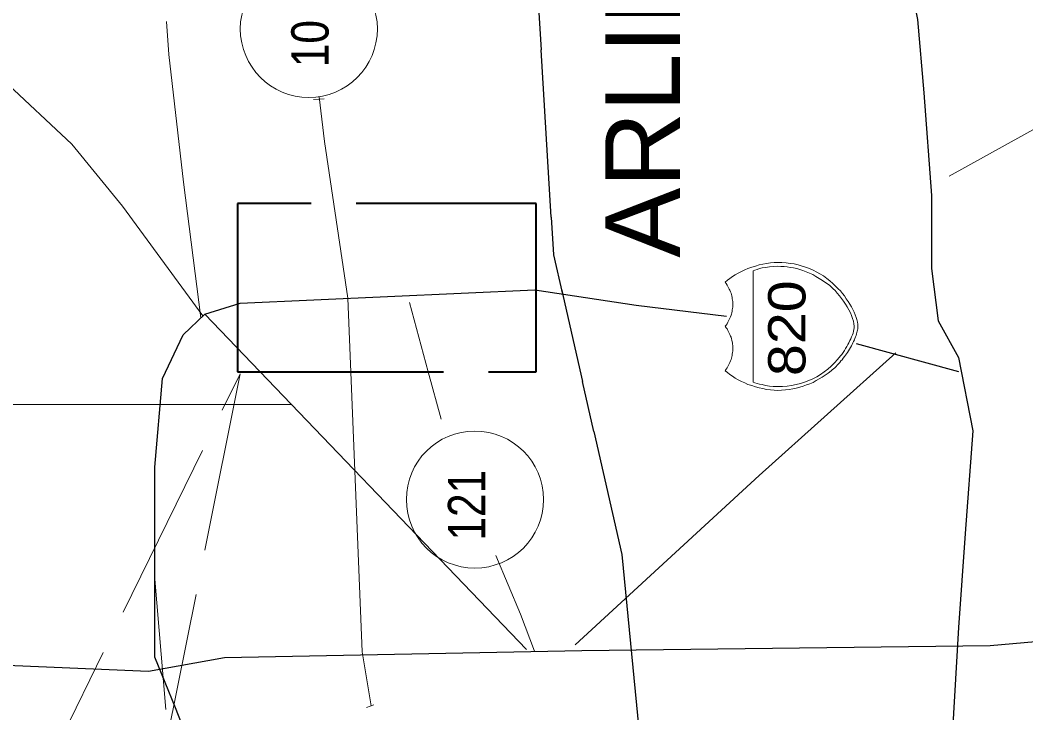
# Model space of a CAD drawing. Extents: x 2363323 to 2367082, y 6956018 to 6980837.
# Drawn here: x 2365927 to 2366064.3, y 6980582.6 to 6980677.3 of the extents above; entities that cross this region are included whole.
import ezdxf

# ---------------------------------------------------------------- set-up
doc = ezdxf.new("R2010")
doc.units = 0
doc.header["$LTSCALE"] = 4.1
doc.linetypes.add('LONG_DASHED', pattern=[7.5, 6, -1.5])
doc.layers.add('62', color=7, linetype='Continuous', lineweight=13)
doc.layers.add('63', color=7, linetype='Continuous', lineweight=13)

msp = doc.modelspace()

# ---------------------------------------------------------------- linework, layer by layer
at = {"layer": '62'}
for p, q in [((2365947.29, 6980672.631), (2365946.952, 6980677.108)), ((2365934.012, 6980660.367), (2365924.697, 6980669.121)), ((2365968.552, 6980660.704), (2365967.789, 6980666.826)), ((2365967.022, 6980666.444), (2365968.484, 6980666.534)), ((2365982.712, 6980629.248), (2365980.144, 6980638.72)), ((2365952.196, 6980637.146), (2365996.139, 6980591.308)), ((2365984.463, 6980622.789), (2365982.712, 6980629.248)), ((2365964.032, 6980624.792), (2365920.176, 6980624.792)), ((2365995.308, 6980596.125), (2365991.957, 6980604.156)), ((2365946.84, 6980583.093), (2365945.334, 6980601.436)), ((2365995.308, 6980596.125), (2365997.22, 6980591.061)), ((2365974.27, 6980583.364), (2365975.283, 6980583.724))]:
    msp.add_line(p, q, dxfattribs=at)
at = {"layer": '62', "lineweight": 25}
for p, q in [((2365999.516, 6980650.396), (2365998.12, 6980673.24)), ((2365957.033, 6980638.607), (2365997.267, 6980640.453)), ((2366000.89, 6980640.543), (2366003.771, 6980627.919)), ((2365952.196, 6980637.146), (2365957.032, 6980638.608)), ((2366041.17, 6980633.096), (2366055.164, 6980629.294)), ((2366005.324, 6980621.103), (2366003.771, 6980627.919))]:
    msp.add_line(p, q, dxfattribs=at)
for points in [[(2365988.154, 6980835.546), (2365989.437, 6980822.404), (2365992.248, 6980802.402), (2365995.06, 6980778.345), (2365996.118, 6980752.4), (2365996.118, 6980723.35), (2365996.997, 6980691.422), (2365998.12, 6980673.24)], [(2366048.01, 6980685.208), (2366049.539, 6980677.378), (2366050.418, 6980667.388), (2366051.476, 6980653.346), (2366051.474, 6980643.356), (2366052.352, 6980636.2), (2366055.164, 6980631.206), (2366057.122, 6980621.192), (2366056.064, 6980607.15), (2366055.164, 6980594.301), (2366054.309, 6980580.237), (2366057.123, 6980558.096), (2366054.309, 6980537.146), (2366050.416, 6980520.246), (2366044.949, 6980510.235), (2366031.738, 6980507.152), (2366018.51, 6980507.151), (2366011.984, 6980505.261), (2366002.646, 6980510.235)], [(2365999.516, 6980650.396), (2365999.808, 6980645.246), (2366001.047, 6980639.868)], [(2365997.267, 6980640.453), (2366011.106, 6980638.338), (2366023.46, 6980636.853)], [(2365973.55, 6980527.155), (2365967.024, 6980537.146), (2365962.275, 6980551.21), (2365957.528, 6980561.2), (2365952.939, 6980571.213), (2365948.169, 6980583.344), (2365945.355, 6980590.252), (2365945.356, 6980600.244), (2365945.356, 6980616.195), (2365946.412, 6980628.348), (2365949.226, 6980634.288), (2365952.196, 6980637.146)], [(2366005.324, 6980621.103), (2366009.171, 6980604.292), (2366011.985, 6980575.242), (2366017.632, 6980553.099), (2366018.038, 6980546.259)], [(2365954.874, 6980590.182), (2366003.705, 6980591.15), (2366059.484, 6980591.828), (2366130.702, 6980598.128), (2366162.138, 6980614.575)], [(2365899.359, 6980590.251), (2365944.478, 6980588.34), (2365954.874, 6980590.182)]]:
    msp.add_lwpolyline(points, dxfattribs=at)
at = {"layer": '62'}
for points in [[(2366168.8, 6980776.882), (2366165.783, 6980768.805), (2366163.94, 6980759.174), (2366160.383, 6980741.87), (2366154.128, 6980731.611), (2366149.72, 6980724.7), (2366143.802, 6980715.788), (2366134.416, 6980706.992), (2366124.222, 6980700.849), (2366112.792, 6980694.908), (2366099.244, 6980686.448), (2366090.672, 6980679.021), (2366082.168, 6980673.328), (2366071.481, 6980667.05), (2366066.596, 6980663.068), (2366053.86, 6980656.002)], [(2365951.632, 6980636.606), (2365949.27, 6980655.168), (2365947.29, 6980672.631)], [(2365934.012, 6980660.367), (2365940.946, 6980651.904), (2365951.902, 6980636.876)], [(2365968.552, 6980660.704), (2365971.728, 6980639.328), (2365973.664, 6980590.971), (2365974.902, 6980583.59)], [(2366023.728, 6980636.2), (2366023.818, 6980636.403), (2366023.91, 6980636.584), (2366023.976, 6980636.763), (2366024.066, 6980636.966), (2366024.111, 6980637.146), (2366024.18, 6980637.326), (2366024.224, 6980637.53), (2366024.246, 6980637.708), (2366024.291, 6980637.91), (2366024.336, 6980638.089), (2366024.336, 6980638.293), (2366024.336, 6980638.496), (2366024.336, 6980638.653), (2366024.336, 6980638.856), (2366024.291, 6980639.058), (2366024.246, 6980639.238), (2366024.225, 6980639.42), (2366024.178, 6980639.62), (2366024.111, 6980639.802), (2366024.066, 6980639.98), (2366023.976, 6980640.184), (2366023.908, 6980640.386), (2366023.818, 6980640.543), (2366023.728, 6980640.746), (2366023.616, 6980640.926), (2366023.524, 6980641.106), (2366023.392, 6980641.306), (2366023.256, 6980641.51), (2366023.571, 6980641.76), (2366023.888, 6980642.006), (2366024.27, 6980642.276), (2366024.651, 6980642.5), (2366025.058, 6980642.726), (2366025.484, 6980642.973), (2366025.935, 6980643.176), (2366026.384, 6980643.356), (2366026.9, 6980643.536), (2366027.396, 6980643.693), (2366027.892, 6980643.85), (2366028.408, 6980643.963), (2366028.926, 6980644.054), (2366029.445, 6980644.12), (2366029.94, 6980644.166), (2366030.48, 6980644.19), (2366031.018, 6980644.166), (2366031.605, 6980644.12), (2366032.168, 6980644.053), (2366032.684, 6980643.987), (2366033.225, 6980643.873), (2366033.764, 6980643.694), (2366034.258, 6980643.537), (2366034.778, 6980643.356), (2366035.271, 6980643.153), (2366035.769, 6980642.884), (2366036.218, 6980642.636), (2366036.693, 6980642.343), (2366037.142, 6980642.006), (2366037.57, 6980641.69), (2366037.996, 6980641.308), (2366038.403, 6980640.927), (2366038.694, 6980640.61), (2366039.01, 6980640.296), (2366039.302, 6980639.958), (2366039.572, 6980639.62), (2366039.82, 6980639.236), (2366040.066, 6980638.856), (2366040.292, 6980638.496), (2366040.516, 6980638.113), (2366040.696, 6980637.776), (2366040.876, 6980637.416), (2366041.034, 6980637.033), (2366041.169, 6980636.674), (2366041.235, 6980636.38), (2366041.328, 6980636.043), (2366041.372, 6980635.752), (2366041.394, 6980635.48)], [(2366041.394, 6980635.48), (2366041.372, 6980635.302), (2366041.372, 6980635.143), (2366041.349, 6980634.94), (2366041.306, 6980634.783), (2366041.259, 6980634.603), (2366041.216, 6980634.423), (2366041.146, 6980634.222), (2366041.079, 6980634.016), (2366040.99, 6980633.817), (2366040.922, 6980633.613), (2366040.809, 6980633.388), (2366040.72, 6980633.21), (2366040.629, 6980632.983), (2366040.518, 6980632.78), (2366040.382, 6980632.556), (2366040.269, 6980632.354), (2366040.134, 6980632.128), (2366039.999, 6980631.903), (2366039.843, 6980631.702), (2366039.706, 6980631.52), (2366039.572, 6980631.318), (2366039.392, 6980631.093), (2366039.234, 6980630.89), (2366039.076, 6980630.733), (2366038.919, 6980630.508), (2366038.762, 6980630.35), (2366038.582, 6980630.148), (2366038.426, 6980629.99), (2366038.244, 6980629.81), (2366038.088, 6980629.653), (2366037.906, 6980629.518), (2366037.726, 6980629.36), (2366037.346, 6980629.066), (2366036.939, 6980628.774), (2366036.532, 6980628.526), (2366036.128, 6980628.302), (2366035.702, 6980628.054), (2366035.272, 6980627.806), (2366034.844, 6980627.626), (2366034.372, 6980627.448), (2366033.944, 6980627.268), (2366033.448, 6980627.133), (2366032.976, 6980627.019), (2366032.504, 6980626.908), (2366032.008, 6980626.816), (2366031.515, 6980626.772), (2366030.974, 6980626.728), (2366030.478, 6980626.704), (2366029.94, 6980626.726), (2366029.444, 6980626.772), (2366028.928, 6980626.84), (2366028.408, 6980626.952), (2366027.892, 6980627.043), (2366027.398, 6980627.2), (2366026.902, 6980627.356), (2366026.384, 6980627.516), (2366025.935, 6980627.718), (2366025.484, 6980627.919), (2366025.058, 6980628.142), (2366024.651, 6980628.392), (2366024.268, 6980628.639), (2366023.886, 6980628.864), (2366023.572, 6980629.136), (2366023.256, 6980629.384), (2366023.391, 6980629.586), (2366023.526, 6980629.788), (2366023.618, 6980629.968), (2366023.727, 6980630.148), (2366023.818, 6980630.35), (2366023.908, 6980630.53), (2366023.976, 6980630.733), (2366024.066, 6980630.936), (2366024.111, 6980631.093), (2366024.178, 6980631.296), (2366024.224, 6980631.476), (2366024.246, 6980631.676), (2366024.291, 6980631.88), (2366024.338, 6980632.06), (2366024.336, 6980632.24), (2366024.338, 6980632.443), (2366024.336, 6980632.623), (2366024.336, 6980632.826), (2366024.291, 6980633.007), (2366024.248, 6980633.208), (2366024.224, 6980633.366), (2366024.18, 6980633.568), (2366024.112, 6980633.77), (2366024.066, 6980633.973), (2366023.976, 6980634.13), (2366023.907, 6980634.333), (2366023.818, 6980634.536), (2366023.728, 6980634.716), (2366023.618, 6980634.897), (2366023.526, 6980635.098), (2366023.392, 6980635.257), (2366023.256, 6980635.48), (2366023.391, 6980635.638), (2366023.526, 6980635.818), (2366023.616, 6980636.02), (2366023.728, 6980636.2)], [(2366046.592, 6980631.836), (2366027.891, 6980615.072), (2366002.758, 6980591.916)]]:
    msp.add_lwpolyline(points, dxfattribs=at)
at = {"layer": '62', "linetype": 'LONG_DASHED', "lineweight": 40}
msp.add_lwpolyline([(2365960.182, 6980629.248), (2365997.468, 6980629.248), (2365997.47, 6980652.267), (2365956.652, 6980652.267), (2365956.65, 6980629.248)], close=True, dxfattribs=at)
at = {"layer": '62'}
msp.add_lwpolyline([(2366027.104, 6980643.063), (2366027.105, 6980627.829), (2366027.328, 6980627.76), (2366027.621, 6980627.648), (2366027.936, 6980627.56), (2366028.342, 6980627.492), (2366028.791, 6980627.379), (2366029.31, 6980627.266), (2366029.848, 6980627.244), (2366030.478, 6980627.222), (2366031.088, 6980627.244), (2366031.738, 6980627.265), (2366032.346, 6980627.38), (2366032.954, 6980627.492), (2366033.561, 6980627.649), (2366034.102, 6980627.829), (2366034.708, 6980628.054), (2366035.248, 6980628.303), (2366035.769, 6980628.573), (2366036.286, 6980628.886), (2366036.806, 6980629.227), (2366037.299, 6980629.587), (2366037.749, 6980630.014), (2366038.198, 6980630.463), (2366038.604, 6980630.934), (2366039.01, 6980631.43), (2366039.212, 6980631.632), (2366039.369, 6980631.903), (2366039.572, 6980632.173), (2366039.729, 6980632.443), (2366039.888, 6980632.69), (2366040.044, 6980632.96), (2366040.179, 6980633.23), (2366040.314, 6980633.523), (2366040.426, 6980633.772), (2366040.539, 6980634.018), (2366040.653, 6980634.288), (2366040.742, 6980634.536), (2366040.81, 6980634.784), (2366040.854, 6980635.008), (2366040.876, 6980635.254), (2366040.899, 6980635.482), (2366040.856, 6980635.796), (2366040.809, 6980636.178), (2366040.674, 6980636.516), (2366040.539, 6980636.943), (2366040.383, 6980637.303), (2366040.158, 6980637.708), (2366039.932, 6980638.113), (2366039.706, 6980638.496), (2366039.438, 6980638.924), (2366039.144, 6980639.283), (2366038.874, 6980639.643), (2366038.583, 6980640.003), (2366038.313, 6980640.34), (2366038.043, 6980640.61), (2366037.749, 6980640.88), (2366037.503, 6980641.083), (2366037.029, 6980641.42), (2366036.578, 6980641.736), (2366036.128, 6980642.006), (2366035.656, 6980642.276), (2366035.226, 6980642.524), (2366034.776, 6980642.726), (2366034.348, 6980642.928), (2366033.898, 6980643.086), (2366033.448, 6980643.243), (2366033.044, 6980643.356), (2366032.595, 6980643.468), (2366032.168, 6980643.513), (2366031.738, 6980643.58), (2366031.312, 6980643.626), (2366030.885, 6980643.648), (2366030.48, 6980643.67), (2366029.848, 6980643.648), (2366029.308, 6980643.603), (2366028.791, 6980643.513), (2366028.341, 6980643.468), (2366027.936, 6980643.357), (2366027.622, 6980643.243), (2366027.33, 6980643.154)], close=True, dxfattribs=at)
at = {"layer": '62', "linetype": 'LONG_DASHED'}
for points in [[(2365927.487, 6980568.808), (2365957.01, 6980628.978), (2365944.929, 6980568.537)], [(2365927.487, 6980568.808), (2365957.01, 6980628.978), (2365944.929, 6980568.537), (2365927.487, 6980568.808)]]:
    msp.add_lwpolyline(points, close=True, dxfattribs=at)
at = {"layer": '62'}
for centre in [(2365966.397, 6980676.102), (2365989.079, 6980611.787)]:
    msp.add_circle(centre, 9.364, dxfattribs=at)
at = {"layer": '63'}
for p, q in [((2365947.29, 6980672.631), (2365946.952, 6980677.108)), ((2365934.012, 6980660.367), (2365924.697, 6980669.121)), ((2365968.552, 6980660.704), (2365967.789, 6980666.826)), ((2365967.022, 6980666.444), (2365968.484, 6980666.534)), ((2365982.712, 6980629.248), (2365980.144, 6980638.72)), ((2365952.196, 6980637.146), (2365996.139, 6980591.308)), ((2365984.463, 6980622.789), (2365982.712, 6980629.248)), ((2365964.032, 6980624.792), (2365920.176, 6980624.792)), ((2365995.308, 6980596.125), (2365991.957, 6980604.156)), ((2365946.84, 6980583.093), (2365945.334, 6980601.436)), ((2365995.308, 6980596.125), (2365997.22, 6980591.061)), ((2365974.27, 6980583.364), (2365975.283, 6980583.724))]:
    msp.add_line(p, q, dxfattribs=at)
at = {"layer": '63', "lineweight": 25}
for p, q in [((2365999.516, 6980650.396), (2365998.12, 6980673.24)), ((2365957.033, 6980638.607), (2365997.267, 6980640.453)), ((2366000.89, 6980640.543), (2366003.771, 6980627.919)), ((2365952.196, 6980637.146), (2365957.032, 6980638.608)), ((2366041.17, 6980633.096), (2366055.164, 6980629.294)), ((2366005.324, 6980621.103), (2366003.771, 6980627.919))]:
    msp.add_line(p, q, dxfattribs=at)
for points in [[(2365988.154, 6980835.546), (2365989.437, 6980822.404), (2365992.248, 6980802.402), (2365995.06, 6980778.345), (2365996.118, 6980752.4), (2365996.118, 6980723.35), (2365996.997, 6980691.422), (2365998.12, 6980673.24)], [(2366048.01, 6980685.208), (2366049.539, 6980677.378), (2366050.418, 6980667.388), (2366051.476, 6980653.346), (2366051.474, 6980643.356), (2366052.352, 6980636.2), (2366055.164, 6980631.206), (2366057.122, 6980621.192), (2366056.064, 6980607.15), (2366055.164, 6980594.301), (2366054.309, 6980580.237), (2366057.123, 6980558.096), (2366054.309, 6980537.146), (2366050.416, 6980520.246), (2366044.949, 6980510.235), (2366031.738, 6980507.152), (2366018.51, 6980507.151), (2366011.984, 6980505.261), (2366002.646, 6980510.235)], [(2365999.516, 6980650.396), (2365999.808, 6980645.246), (2366001.047, 6980639.868)], [(2365997.267, 6980640.453), (2366011.106, 6980638.338), (2366023.46, 6980636.853)], [(2365973.55, 6980527.155), (2365967.024, 6980537.146), (2365962.275, 6980551.21), (2365957.528, 6980561.2), (2365952.939, 6980571.213), (2365948.169, 6980583.344), (2365945.355, 6980590.252), (2365945.356, 6980600.244), (2365945.356, 6980616.195), (2365946.412, 6980628.348), (2365949.226, 6980634.288), (2365952.196, 6980637.146)], [(2366005.324, 6980621.103), (2366009.171, 6980604.292), (2366011.985, 6980575.242), (2366017.632, 6980553.099), (2366018.038, 6980546.259)], [(2365954.874, 6980590.182), (2366003.705, 6980591.15), (2366059.484, 6980591.828), (2366130.702, 6980598.128), (2366162.138, 6980614.575)], [(2365899.359, 6980590.251), (2365944.478, 6980588.34), (2365954.874, 6980590.182)]]:
    msp.add_lwpolyline(points, dxfattribs=at)
at = {"layer": '63'}
for points in [[(2366168.8, 6980776.882), (2366165.783, 6980768.805), (2366163.94, 6980759.174), (2366160.383, 6980741.87), (2366154.128, 6980731.611), (2366149.72, 6980724.7), (2366143.802, 6980715.788), (2366134.416, 6980706.992), (2366124.222, 6980700.849), (2366112.792, 6980694.908), (2366099.244, 6980686.448), (2366090.672, 6980679.021), (2366082.168, 6980673.328), (2366071.481, 6980667.05), (2366066.596, 6980663.068), (2366053.86, 6980656.002)], [(2365951.632, 6980636.606), (2365949.27, 6980655.168), (2365947.29, 6980672.631)], [(2365934.012, 6980660.367), (2365940.946, 6980651.904), (2365951.902, 6980636.876)], [(2365968.552, 6980660.704), (2365971.728, 6980639.328), (2365973.664, 6980590.971), (2365974.902, 6980583.59)], [(2366023.728, 6980636.2), (2366023.818, 6980636.403), (2366023.91, 6980636.584), (2366023.976, 6980636.763), (2366024.066, 6980636.966), (2366024.111, 6980637.146), (2366024.18, 6980637.326), (2366024.224, 6980637.53), (2366024.246, 6980637.708), (2366024.291, 6980637.91), (2366024.336, 6980638.089), (2366024.336, 6980638.293), (2366024.336, 6980638.496), (2366024.336, 6980638.653), (2366024.336, 6980638.856), (2366024.291, 6980639.058), (2366024.246, 6980639.238), (2366024.225, 6980639.42), (2366024.178, 6980639.62), (2366024.111, 6980639.802), (2366024.066, 6980639.98), (2366023.976, 6980640.184), (2366023.908, 6980640.386), (2366023.818, 6980640.543), (2366023.728, 6980640.746), (2366023.616, 6980640.926), (2366023.524, 6980641.106), (2366023.392, 6980641.306), (2366023.256, 6980641.51), (2366023.571, 6980641.76), (2366023.888, 6980642.006), (2366024.27, 6980642.276), (2366024.651, 6980642.5), (2366025.058, 6980642.726), (2366025.484, 6980642.973), (2366025.935, 6980643.176), (2366026.384, 6980643.356), (2366026.9, 6980643.536), (2366027.396, 6980643.693), (2366027.892, 6980643.85), (2366028.408, 6980643.963), (2366028.926, 6980644.054), (2366029.445, 6980644.12), (2366029.94, 6980644.166), (2366030.48, 6980644.19), (2366031.018, 6980644.166), (2366031.605, 6980644.12), (2366032.168, 6980644.053), (2366032.684, 6980643.987), (2366033.225, 6980643.873), (2366033.764, 6980643.694), (2366034.258, 6980643.537), (2366034.778, 6980643.356), (2366035.271, 6980643.153), (2366035.769, 6980642.884), (2366036.218, 6980642.636), (2366036.693, 6980642.343), (2366037.142, 6980642.006), (2366037.57, 6980641.69), (2366037.996, 6980641.308), (2366038.403, 6980640.927), (2366038.694, 6980640.61), (2366039.01, 6980640.296), (2366039.302, 6980639.958), (2366039.572, 6980639.62), (2366039.82, 6980639.236), (2366040.066, 6980638.856), (2366040.292, 6980638.496), (2366040.516, 6980638.113), (2366040.696, 6980637.776), (2366040.876, 6980637.416), (2366041.034, 6980637.033), (2366041.169, 6980636.674), (2366041.235, 6980636.38), (2366041.328, 6980636.043), (2366041.372, 6980635.752), (2366041.394, 6980635.48)], [(2366041.394, 6980635.48), (2366041.372, 6980635.302), (2366041.372, 6980635.143), (2366041.349, 6980634.94), (2366041.306, 6980634.783), (2366041.259, 6980634.603), (2366041.216, 6980634.423), (2366041.146, 6980634.222), (2366041.079, 6980634.016), (2366040.99, 6980633.817), (2366040.922, 6980633.613), (2366040.809, 6980633.388), (2366040.72, 6980633.21), (2366040.629, 6980632.983), (2366040.518, 6980632.78), (2366040.382, 6980632.556), (2366040.269, 6980632.354), (2366040.134, 6980632.128), (2366039.999, 6980631.903), (2366039.843, 6980631.702), (2366039.706, 6980631.52), (2366039.572, 6980631.318), (2366039.392, 6980631.093), (2366039.234, 6980630.89), (2366039.076, 6980630.733), (2366038.919, 6980630.508), (2366038.762, 6980630.35), (2366038.582, 6980630.148), (2366038.426, 6980629.99), (2366038.244, 6980629.81), (2366038.088, 6980629.653), (2366037.906, 6980629.518), (2366037.726, 6980629.36), (2366037.346, 6980629.066), (2366036.939, 6980628.774), (2366036.532, 6980628.526), (2366036.128, 6980628.302), (2366035.702, 6980628.054), (2366035.272, 6980627.806), (2366034.844, 6980627.626), (2366034.372, 6980627.448), (2366033.944, 6980627.268), (2366033.448, 6980627.133), (2366032.976, 6980627.019), (2366032.504, 6980626.908), (2366032.008, 6980626.816), (2366031.515, 6980626.772), (2366030.974, 6980626.728), (2366030.478, 6980626.704), (2366029.94, 6980626.726), (2366029.444, 6980626.772), (2366028.928, 6980626.84), (2366028.408, 6980626.952), (2366027.892, 6980627.043), (2366027.398, 6980627.2), (2366026.902, 6980627.356), (2366026.384, 6980627.516), (2366025.935, 6980627.718), (2366025.484, 6980627.919), (2366025.058, 6980628.142), (2366024.651, 6980628.392), (2366024.268, 6980628.639), (2366023.886, 6980628.864), (2366023.572, 6980629.136), (2366023.256, 6980629.384), (2366023.391, 6980629.586), (2366023.526, 6980629.788), (2366023.618, 6980629.968), (2366023.727, 6980630.148), (2366023.818, 6980630.35), (2366023.908, 6980630.53), (2366023.976, 6980630.733), (2366024.066, 6980630.936), (2366024.111, 6980631.093), (2366024.178, 6980631.296), (2366024.224, 6980631.476), (2366024.246, 6980631.676), (2366024.291, 6980631.88), (2366024.338, 6980632.06), (2366024.336, 6980632.24), (2366024.338, 6980632.443), (2366024.336, 6980632.623), (2366024.336, 6980632.826), (2366024.291, 6980633.007), (2366024.248, 6980633.208), (2366024.224, 6980633.366), (2366024.18, 6980633.568), (2366024.112, 6980633.77), (2366024.066, 6980633.973), (2366023.976, 6980634.13), (2366023.907, 6980634.333), (2366023.818, 6980634.536), (2366023.728, 6980634.716), (2366023.618, 6980634.897), (2366023.526, 6980635.098), (2366023.392, 6980635.257), (2366023.256, 6980635.48), (2366023.391, 6980635.638), (2366023.526, 6980635.818), (2366023.616, 6980636.02), (2366023.728, 6980636.2)], [(2366046.592, 6980631.836), (2366027.891, 6980615.072), (2366002.758, 6980591.916)]]:
    msp.add_lwpolyline(points, dxfattribs=at)
at = {"layer": '63', "linetype": 'LONG_DASHED', "lineweight": 40}
msp.add_lwpolyline([(2365960.182, 6980629.248), (2365997.468, 6980629.248), (2365997.47, 6980652.267), (2365956.652, 6980652.267), (2365956.65, 6980629.248)], close=True, dxfattribs=at)
at = {"layer": '63'}
msp.add_lwpolyline([(2366027.104, 6980643.063), (2366027.105, 6980627.829), (2366027.328, 6980627.76), (2366027.621, 6980627.648), (2366027.936, 6980627.56), (2366028.342, 6980627.492), (2366028.791, 6980627.379), (2366029.31, 6980627.266), (2366029.848, 6980627.244), (2366030.478, 6980627.222), (2366031.088, 6980627.244), (2366031.738, 6980627.265), (2366032.346, 6980627.38), (2366032.954, 6980627.492), (2366033.561, 6980627.649), (2366034.102, 6980627.829), (2366034.708, 6980628.054), (2366035.248, 6980628.303), (2366035.769, 6980628.573), (2366036.286, 6980628.886), (2366036.806, 6980629.227), (2366037.299, 6980629.587), (2366037.749, 6980630.014), (2366038.198, 6980630.463), (2366038.604, 6980630.934), (2366039.01, 6980631.43), (2366039.212, 6980631.632), (2366039.369, 6980631.903), (2366039.572, 6980632.173), (2366039.729, 6980632.443), (2366039.888, 6980632.69), (2366040.044, 6980632.96), (2366040.179, 6980633.23), (2366040.314, 6980633.523), (2366040.426, 6980633.772), (2366040.539, 6980634.018), (2366040.653, 6980634.288), (2366040.742, 6980634.536), (2366040.81, 6980634.784), (2366040.854, 6980635.008), (2366040.876, 6980635.254), (2366040.899, 6980635.482), (2366040.856, 6980635.796), (2366040.809, 6980636.178), (2366040.674, 6980636.516), (2366040.539, 6980636.943), (2366040.383, 6980637.303), (2366040.158, 6980637.708), (2366039.932, 6980638.113), (2366039.706, 6980638.496), (2366039.438, 6980638.924), (2366039.144, 6980639.283), (2366038.874, 6980639.643), (2366038.583, 6980640.003), (2366038.313, 6980640.34), (2366038.043, 6980640.61), (2366037.749, 6980640.88), (2366037.503, 6980641.083), (2366037.029, 6980641.42), (2366036.578, 6980641.736), (2366036.128, 6980642.006), (2366035.656, 6980642.276), (2366035.226, 6980642.524), (2366034.776, 6980642.726), (2366034.348, 6980642.928), (2366033.898, 6980643.086), (2366033.448, 6980643.243), (2366033.044, 6980643.356), (2366032.595, 6980643.468), (2366032.168, 6980643.513), (2366031.738, 6980643.58), (2366031.312, 6980643.626), (2366030.885, 6980643.648), (2366030.48, 6980643.67), (2366029.848, 6980643.648), (2366029.308, 6980643.603), (2366028.791, 6980643.513), (2366028.341, 6980643.468), (2366027.936, 6980643.357), (2366027.622, 6980643.243), (2366027.33, 6980643.154)], close=True, dxfattribs=at)
at = {"layer": '63', "linetype": 'LONG_DASHED'}
for points in [[(2365927.487, 6980568.808), (2365957.01, 6980628.978), (2365944.929, 6980568.537)], [(2365927.487, 6980568.808), (2365957.01, 6980628.978), (2365944.929, 6980568.537), (2365927.487, 6980568.808)]]:
    msp.add_lwpolyline(points, close=True, dxfattribs=at)
at = {"layer": '63'}
for centre in [(2365966.397, 6980676.102), (2365989.079, 6980611.787)]:
    msp.add_circle(centre, 9.364, dxfattribs=at)

# ---------------------------------------------------------------- texts
at = {"layer": '62'}
for s, height, width, p in [('ARLINGTON', 10.21, 1.05, (2366017.091, 6980644.842)), ('10', 5.099, 0.85, (2365969.093, 6980670.876)), ('820', 5.099, 1.15, (2366034.237, 6980628.662)), ('121', 5.099, 0.85, (2365990.492, 6980606.184))]:
    msp.add_text(s, height=height, rotation=90, dxfattribs=dict(at, width=width)).set_placement(p)
at = {"layer": '63'}
for s, height, width, p in [('ARLINGTON', 10.21, 1.05, (2366017.091, 6980644.842)), ('10', 5.099, 0.85, (2365969.093, 6980670.876)), ('820', 5.099, 1.15, (2366034.237, 6980628.662)), ('121', 5.099, 0.85, (2365990.492, 6980606.184))]:
    msp.add_text(s, height=height, rotation=90, dxfattribs=dict(at, width=width)).set_placement(p)

doc.saveas('drawing.dxf')
